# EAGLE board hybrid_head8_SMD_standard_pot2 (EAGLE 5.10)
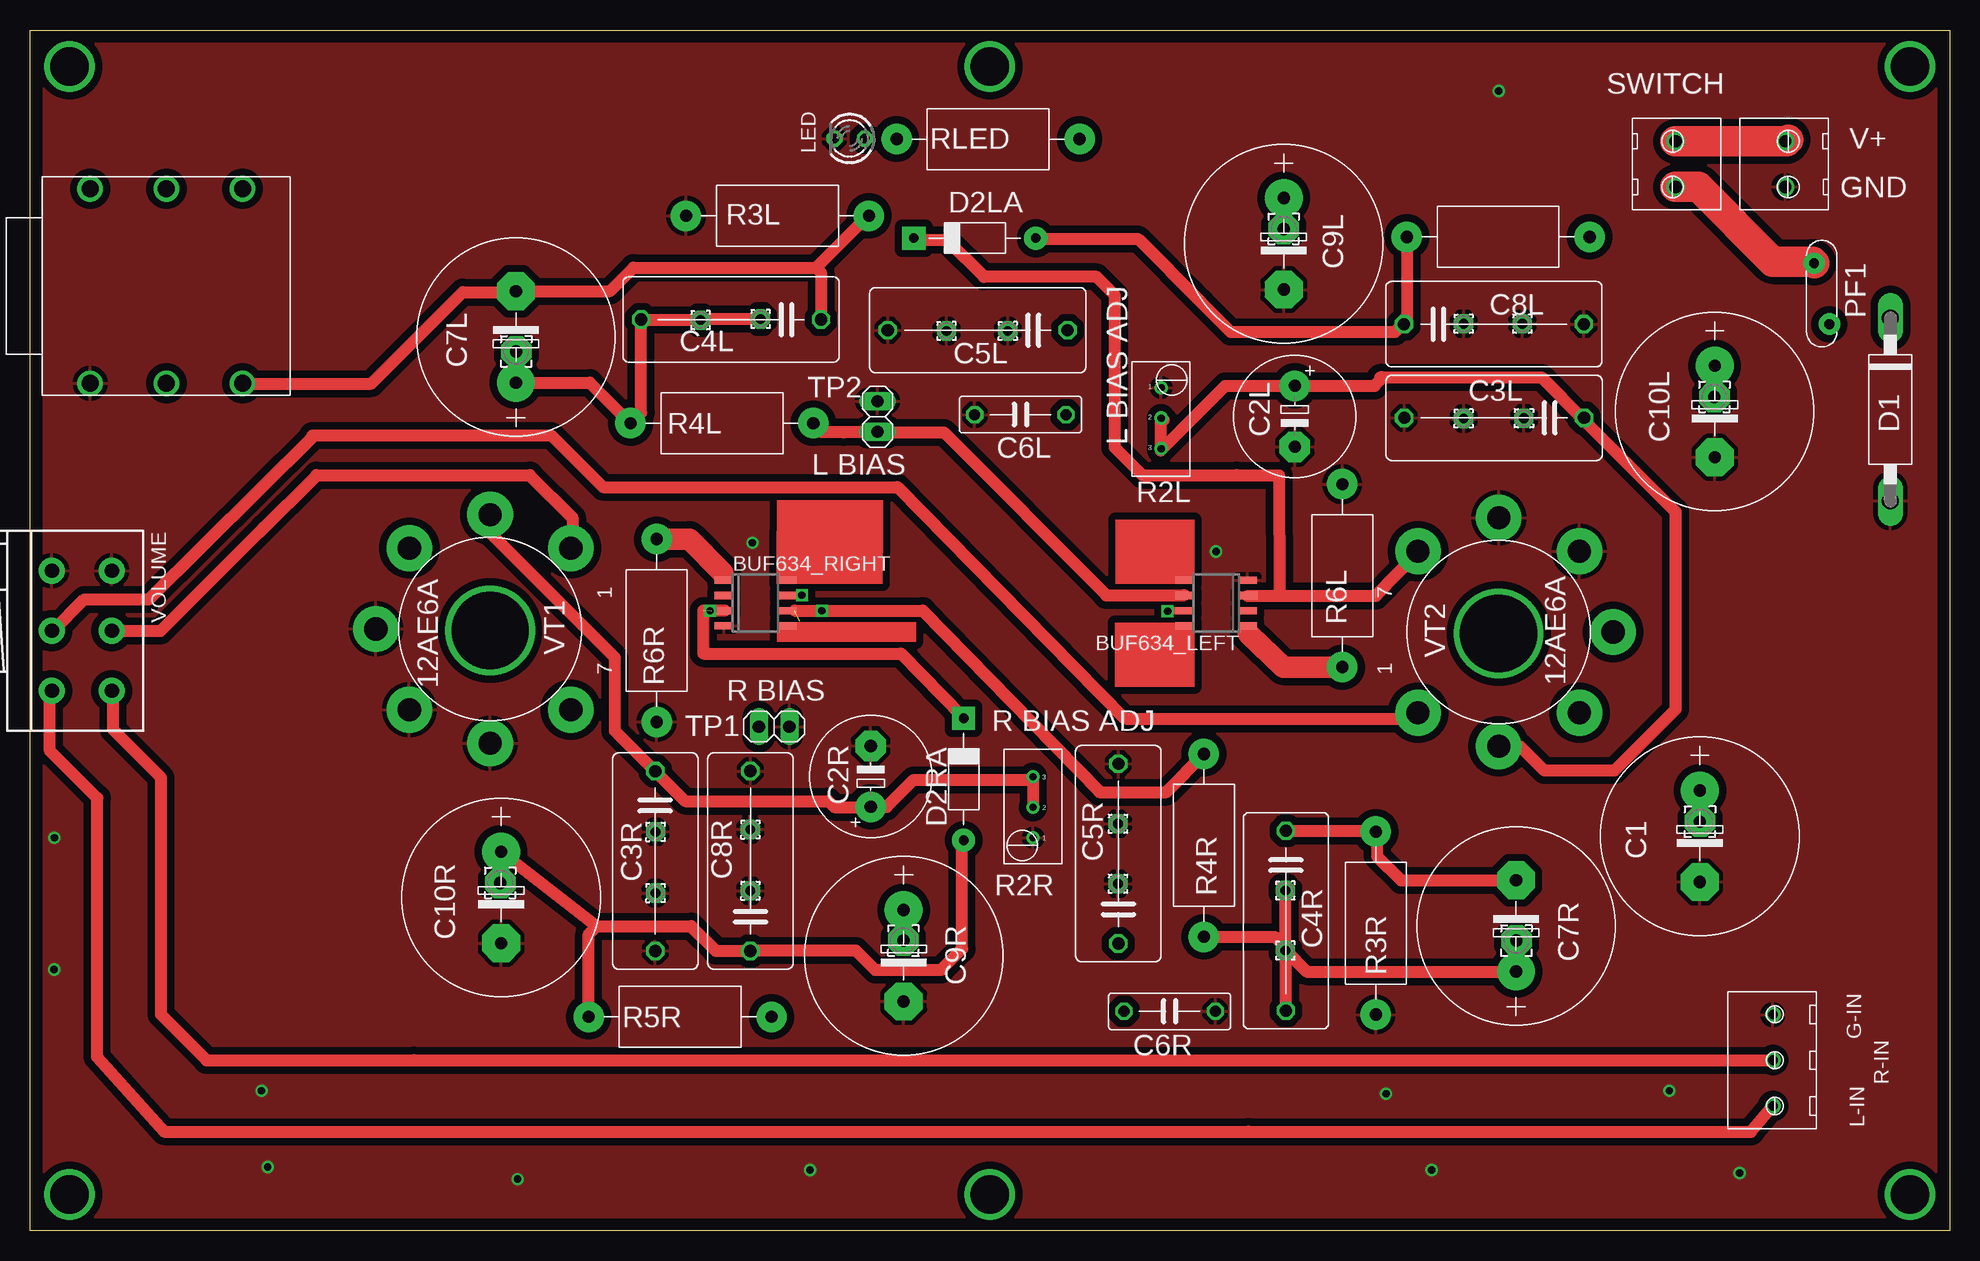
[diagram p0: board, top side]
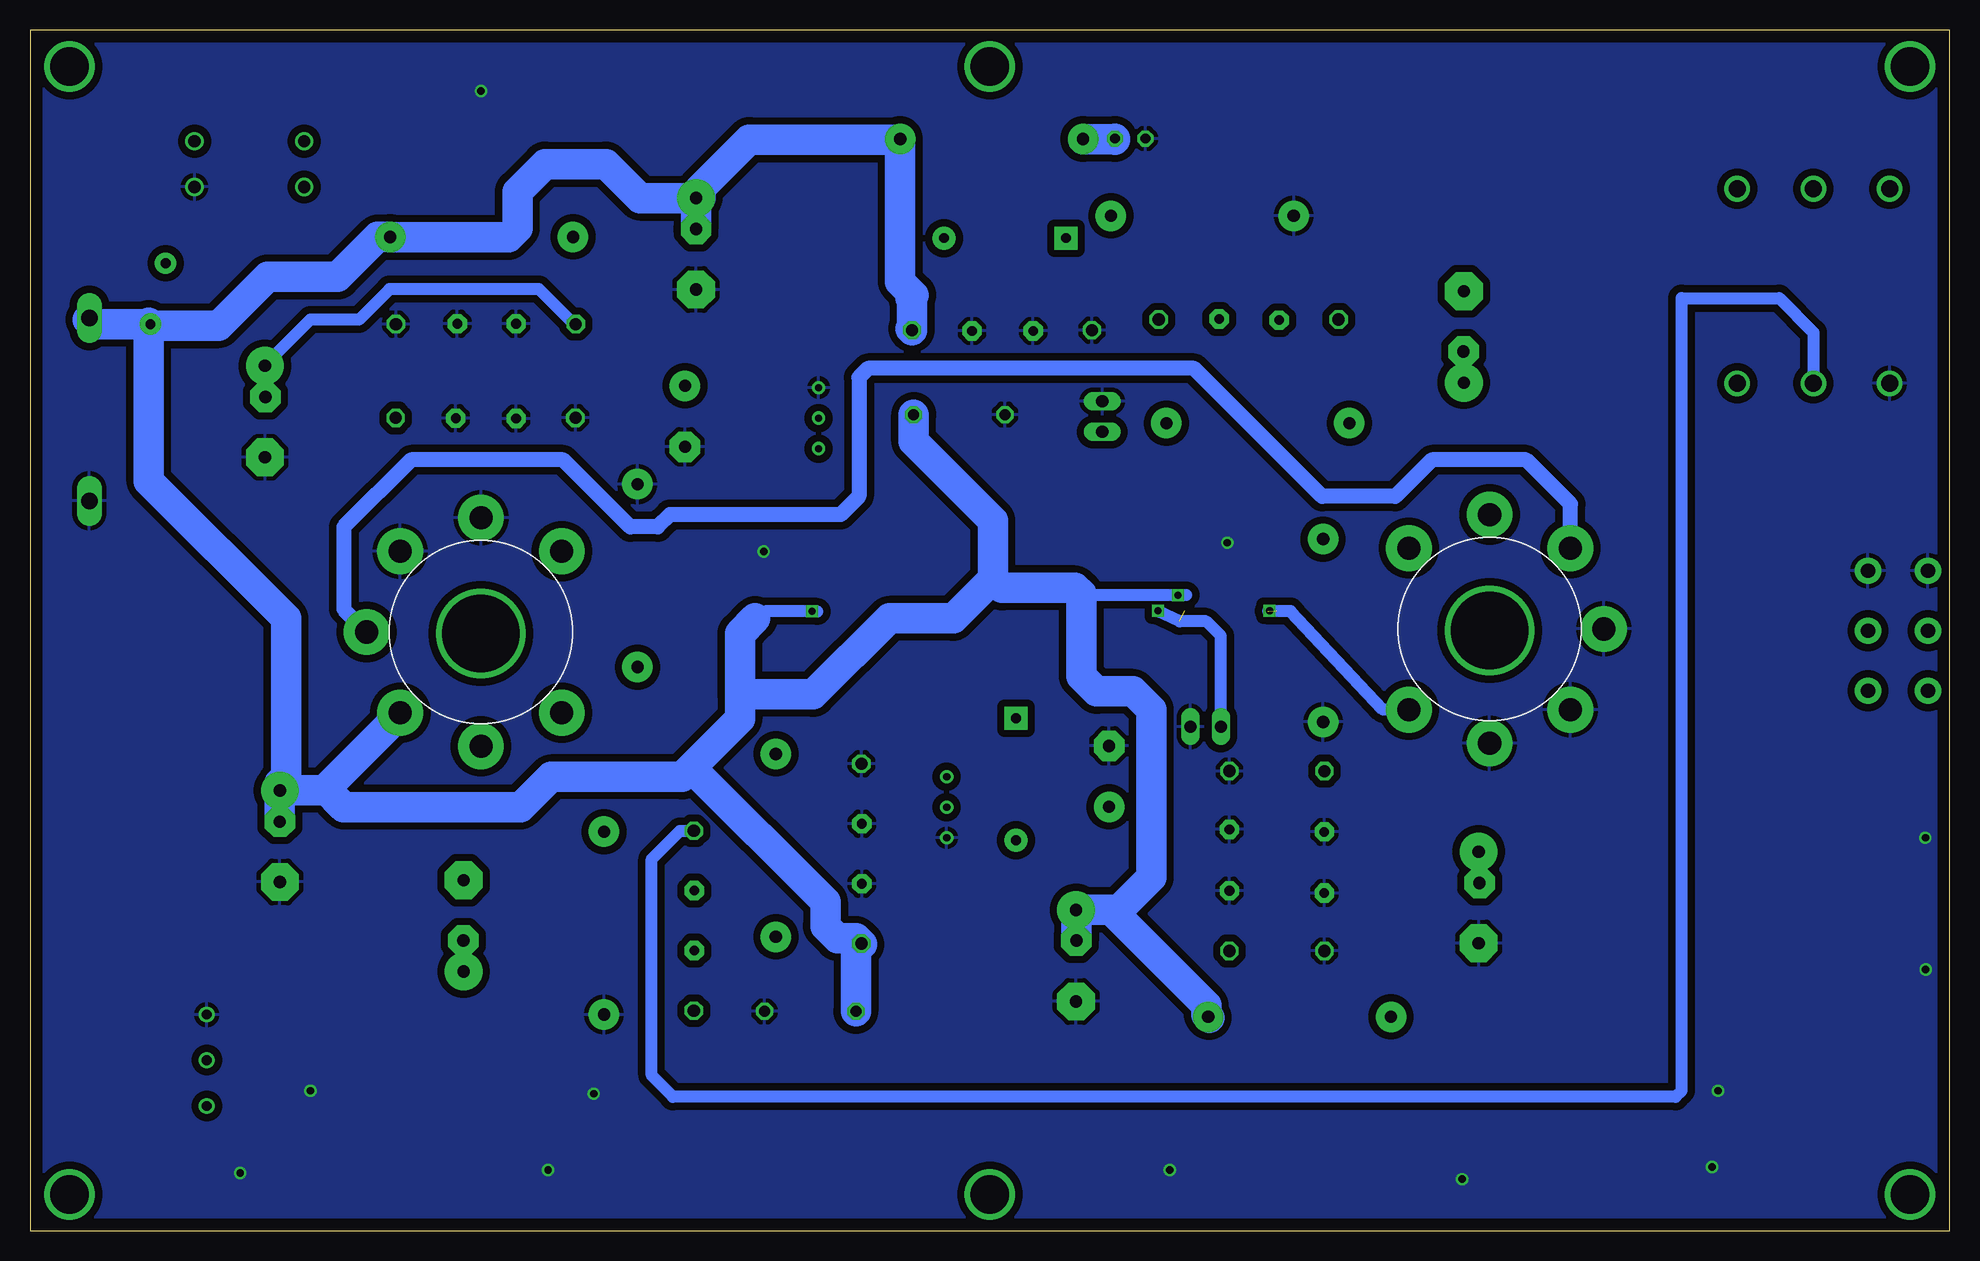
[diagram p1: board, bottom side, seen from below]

Size 160.02 x 100.08 mm. Coordinates in mm from the lower left corner, seen from the top.
Outline: 0,100.08 160.02,100.08 160.02,0 0,0 0,100.08
Copper layers (1*16): Top 0.035mm / dielectric 1.5mm / Bottom 0.035mm
Design rules "default": minimum track width 10mil, minimum drill 24mil, track to track 20mil, track to pad 20mil, pad to pad 20mil, via to via 20mil, smd to smd 8mil, copper to edge 40mil, drill to drill 8mil, minimum pad ring 10mil, minimum via ring 8mil, stop-mask expansion 0mil, vias tented up to drill 0mil, thermal gap 15mil

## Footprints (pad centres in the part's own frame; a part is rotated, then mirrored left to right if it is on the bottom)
SO8 = smd 0.6 x 1.6: 1 -1.905,-2.6; 2 -0.635,-2.6; 3 0.635,-2.6; 4 1.905,-2.6; 5 1.905,2.6; 6 0.635,2.6; 7 -0.635,2.6; 8 -1.905,2.6
E7,5-16 = drill 1.016 pad 3.15 round: + -3.81,0 | drill 1.016 pad 3.15 octagon: - 3.81,0
E5-10,5 = drill 1.016 pad 2.54 round: + -2.54,0 | drill 1.016 pad 2.54 octagon: - 2.54,0
C150-072X183 = drill 1.016 octagon: 1 -7.493,0; 2 7.493,0
C075-032X103 = drill 0.914 octagon: 1 -3.81,0; 2 3.81,0
CB417-15 = drill 1.397 long: A 7.62,0; K -7.62,0
DO35 = drill 0.813 pad 1.93 square: 1 -5.08,0 | drill 0.813 pad 1.93 round: 2 5.08,0
2,54/1,0 = drill 1.016 pad 2.54 octagon: 1 0,0
1,6/0,8 = drill 0.813 pad 1.6 octagon: 1 0,0
158-PO2EK381V2 = drill 1.016 round: P$1 1.905,0; P$2 -1.905,0
158-P02EK381V3 = drill 0.813 round: P$1 0,0; P$2 -3.81,0; P$3 3.81,0
NMJ6HCD2 = drill 1.422 round: P$1 -8.11,4; P$2 8.11,4; P$3 8.11,10.35; P$4 -8.11,10.35; P$5 -8.11,16.7; P$6 8.11,16.7
LED3MM = drill 0.813 octagon: A -1.27,0; K 1.27,0
RXE050 = drill 0.813 pad 1.778 round: P$1 -0.635,2.54; P$2 0.635,-2.54
3296W = drill 0.6 round: P$1 2.413,7.239; P$2 2.413,4.699; P$3 2.413,2.159
R1/2W = drill 1.016 pad 2.54 round: P$1 0,0; P$2 15.24,0
1X02 = drill 1.016 long: 1 -1.27,0; 2 1.27,0
3RP/1610G = drill 1.2 pad 2.184 round: 1-1 -5,0; 1-2 0,0; 1-3 5,0; 2-1 -5,5; 2-2 0,5; 2-3 5,5
MINI7_PCB = drill 1.93 pad 3.81 round: 1 6.731,-6.731; 2 9.525,0; 3 6.731,6.731; 4 0,9.525; 5 -6.731,6.731; 6 -9.525,0; 7 -6.731,-6.731

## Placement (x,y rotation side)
BUF634_LEFT  [SO8]  98.87,52.32 90 top
BUF634_RIGHT  [SO8]  60.45,52.32 270 top
C1  100UF_100V  [E7,5-16]  139.19,32.89 270 top
C2L  220UF_16V  [E5-10,5]  105.43,67.89 270 top
C2R  220UF_16V  [E5-10,5]  70.08,37.87 90 top
C3L  0.22UF_50V  [C150-072X183]  122.04,67.75 180 top
C3R  0.22UF_50V  [C150-072X183]  52.12,30.82 270 top
C4L  0.22UF_50V  [C150-072X183]  58.44,75.95 180 top
C4R  0.22UF_50V  [C150-072X183]  104.69,25.85 270 top
C5L  0.22UF_50V  [C150-072X183]  79,75.06 180 top
C5R  0.22UF_50V  [C150-072X183]  90.72,31.44 90 top
C6L  .01UF_50V  [C075-032X103]  82.56,68.03 0 top
C6R  .01UF_50V  [C075-032X103]  94.99,18.3 180 top
C7L  100UF_100V  [E7,5-16]  40.51,74.5 90 top
C7R  100UF_100V  [E7,5-16]  123.87,25.42 90 top
C8L  0.22UF_50V  [C150-072X183]  122.02,75.56 0 top
C8R  0.22UF_50V  [C150-072X183]  60.05,30.83 90 top
C9L  100UF_100V  [E7,5-16]  104.51,82.26 270 top
C9R  100UF_100V  [E7,5-16]  72.82,22.93 270 top
C10L  100UF_100V  [E7,5-16]  140.43,68.28 270 top
C10R  100UF_100V  [E7,5-16]  39.27,27.79 270 top
D1  P6KE30  [CB417-15]  155.07,68.45 270 top
D2LA  1N5291  [DO35]  78.75,82.73 0 top
D2RA  1N5291  [DO35]  77.83,37.64 270 top
E$2  [2,54/1,0]  40.53,73.29 0 top
E$3  [1,6/0,8]  52.14,33.25 90 top
E$4  [1,6/0,8]  52.14,28.15 90 top
E$5  [1,6/0,8]  60.04,33.45 90 top
E$6  [1,6/0,8]  60.04,28.35 90 top
E$7  [1,6/0,8]  90.68,28.93 90 top
E$9  [1,6/0,8]  90.68,33.93 90 top
E$10  [1,6/0,8]  104.65,28.36 270 top
E$11  [1,6/0,8]  104.65,23.36 270 top
E$12  [1,6/0,8]  124.53,67.72 0 top
E$13  [1,6/0,8]  119.5,67.7 0 top
E$14  [1,6/0,8]  119.5,75.6 0 top
E$15  [1,6/0,8]  124.4,75.6 0 top
E$16  [1,6/0,8]  81.5,75 0 top
E$17  [1,6/0,8]  76.4,75 0 top
E$18  [1,6/0,8]  55.9,75.9 0 top
E$19  [1,6/0,8]  60.9,76 0 top
E$20  [2,54/1,0]  104.5,83.5 0 top
E$21  [2,54/1,0]  140.4,69.5 0 top
E$22  [2,54/1,0]  139.2,34.1 0 top
E$23  [2,54/1,0]  123.9,24.2 0 top
E$24  [2,54/1,0]  72.8,24.2 0 top
E$25  [2,54/1,0]  39.2,29 0 top
E$26  [158-PO2EK381V2]  137.16,88.9 270 top
E$29  [158-PO2EK381V2]  146.3,88.9 90 top
E$30  [158-P02EK381V3]  145.29,14.22 90 top
E$31  [NMJ6HCD2]  1.02,78.74 270 top
LED  [LED3MM]  68.32,91.03 180 top
PF1  RXE050  [RXE050]  149.35,78.11 0 top
R2  [3296W]  81.19,30.6 0 top
R3L  1K  [R1/2W]  54.69,84.59 0 top
R3R  1K  [R1/2W]  112.18,18.03 90 top
R4L  22  [R1/2W]  65.29,67.31 180 top
R4R  22  [R1/2W]  97.85,39.75 270 top
R5L  1K  [R1/2W]  114.76,82.83 0 top
R5R  1K  [R1/2W]  46.57,17.83 0 top
R6  [3296W]  96.7,72.43 180 top
R6L  1K  [R1/2W]  109.38,46.98 90 top
R6R  1K  [R1/2W]  52.23,42.41 90 top
RLED  1K  [R1/2W]  87.48,90.99 180 top
TP1  [1X02]  62.02,42.02 0 top
TP2  [1X02]  70.64,67.86 90 top
VOLUME  [3RP/1610G]  1.82,50.01 270 top
VT1  12AE6A  [MINI7_PCB]  38.35,50.16 90 top
VT2  12AE6A  [MINI7_PCB]  122.43,49.91 270 top

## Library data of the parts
BUF634_LEFT BUF634_RIGHT = micro-philips
C1 C7L C7R C9L C9R C10L C10R = polcap
C2L C2R C3L C3R C4L C4R C5L C5R C6L C6R C8L C8R = rcl
D1 = diode
D2LA D2RA PF1 R3L R3R R4L R4R R5L R5R R6L R6R RLED VT1 VT2 = wheat
E$2-E$7 E$9-E$25 = wirepad2
E$26 E$29 E$30 = con-kobiconn2
E$31 = neutrik
LED = led
R2 R6 = bourns
TP1 TP2 = pinhead
VOLUME = pot

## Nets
B+L: C8L.1 C10L.+ E$21.1 R5L.P$1
B+R: C8R.1 C10R.+ D2RA.2 E$25.1 R5R.P$1
BUF_L: R4L.P$1 TP2.1
BUF_R: TP1.1
CAP_L: C4L.2 C7L.+ E$2.1 E$18.1 E$19.1 R4L.P$2
CAP_R: C4R.2 C7R.+ E$10.1 E$11.1 E$23.1 R4R.P$2
DCSW: E$26.P$1 PF1.P$1
GND: BUF634_LEFT.4 BUF634_RIGHT.4 C1.- C2L.- C2R.- C3L.2 C3R.2 C5L.2 C5R.2 C6L.1 C6R.1 C8L.2 C8R.2 C9L.- C9R.- C10L.- C10R.- D1.A E$3.1 E$4.1 E$5.1 E$6.1 E$7.1 E$9.1 E$12.1 E$13.1 E$14.1 E$15.1 E$16.1 E$17.1 E$29.P$2 E$30.P$3 E$31.P$2 LED.K R2.P$3 R3L.P$1 R3R.P$1 R6.P$3 R6L.P$2 R6R.P$1 TP1.2 TP2.2 VOLUME.1-1 VOLUME.2-1 VT1.4 VT1.5 VT1.6 VT2.5 VT2.6
K_L: C2L.+ C3L.1 R6.P$1 R6.P$2 VT2.2
K_R: C2R.+ C3R.1 R2.P$1 R2.P$2 VT1.2
L_IN: E$30.P$2
LED: LED.A RLED.P$2
OUT_L: C4L.1 C7L.- E$31.P$6 R3L.P$2
OUT_R: C4R.1 C7R.- E$31.P$3 R3R.P$2
P_L: D2LA.1
P_R: VT1.7
R_IN: E$30.P$1
RIGHT_SIGNAL: VT1.1
S$1: VT1.3 VT2.4
S$17: VT2.7
S$22: D2RA.1
S$23: R4R.P$1
S$25: VT2.1
S$28: R6L.P$1
V+: C1.+ C5L.1 C5R.1 C6L.2 C6R.2 C9L.+ C9R.+ D1.K E$20.1 E$22.1 E$24.1 PF1.P$2 R5L.P$2 R5R.P$2 RLED.P$1 VT2.3
V_IN: E$26.P$2 E$29.P$1

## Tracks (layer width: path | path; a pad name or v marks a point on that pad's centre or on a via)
B+L
  Top 1.016: E$21.1 140.43,69.53 | C10L.+ 140.51,72.08 | R5L.P$1 114.78,82.8 114.81,82.8 114.81,75.95 114.53,75.67 | 114.53,75.42 C8L.1 114.53,75.67 | 114.53,75.67 113.79,74.93 100.08,74.93 96.77,78.23
  Bottom 1.016: E$21.1 140.4,69.53 140.46,69.6 140.43,69.63 C10L.+ 140.43,72.1 140.46,72.14 136.65,75.95 132.59,75.95 130.05,78.49 117.6,78.49 114.55,75.44 114.53,75.46 C8L.1
B+R
  Top 1.016: 47.24,25.4 55.12,25.4 57.19,23.33 C8R.1 59.98,23.33 59.94,23.37 68.83,23.37 70.45,21.75 75.95,21.75 77.7,23.5 77.7,32.49 77.78,32.56 D2RA.2 | 47.24,25.4 39.37,31.5 39.22,31.6 C10R.+ 39.2,31.6 E$25.1 | 47.24,25.4 46.57,24.73 R5R.P$1
BUF_L
  Top 1.016: 70.61,66.55 TP2.1 67.82,66.59 | 67.82,66.59 67.82,66.55 | 67.82,66.59 66,66.59 65.28,67.31 R4L.P$1
BUF_R  (1 unrouted)
  Top 1.016: 89.13,36.58 74.4,51.7 63.73,51.7
  Bottom 1.016: 65.98,51.63 64.19,50.8 61.98,50.8 60.75,49.58 TP1.1
CAP_L
  Top 1.016: 50.04,67.31 46.66,70.69 C7L.+ 40.5,73.29 E$2.1 | E$19.1 55.93,76 55.88,75.95 | 55.88,75.95 55.9,75.93 E$18.1 | 55.88,75.95 C4L.2 50.95,68.22 50.04,67.31 | 50.04,67.31 R4L.P$2
  Bottom 1.016: R4L.P$2 50.04,67.31
CAP_R
  Top 1.016: E$11.1 104.9,23.36 104.9,23.37 103.76,24.51 R4R.P$2 | C4R.2 104.69,18.33 104.65,18.29 E$11.1 | 104.65,28.45 E$10.1 | E$11.1 104.65,28.45 | 104.65,28.45 104.39,28.7 | E$11.1 | E$11.1 106.4,21.61 C7R.+ 123.87,24.17 E$23.1
DCSW
  Top 2.54: E$26.P$1 139.06,87 145.29,80.77 148.59,80.77 PF1.P$1
GND  (via drill 0.61)
  other vias: 2.01,21.78 116.84,5.08 136.65,11.68 122.43,95 2.03,32.77 142.49,4.83 19.81,5.33 40.64,4.32 19.3,11.68 65.02,5.08 113.03,11.43 98.87,56.61 60.22,57.35
  pour Top (isolate 0.61): 0,0 160.02,0 160.02,100.08 0,100.08
  pour Bottom (isolate 0.61): 0,0 160.02,0 160.02,100.08 0,100.08
K_L
  Top 1.016: 105.32,70.44 105.41,70.36 105.43,70.37 C2L.+ | C2L.+ 112.08,70.43 112.78,71.12 | 112.78,71.12 125.73,71.12 | 112.78,71.12 112.52,71.12 | 112.78,71.12 125.98,71.12 129.54,67.57 | 129.54,67.57 129.54,67.56 | 129.54,67.57 C3L.1 | 129.54,67.57 137.16,59.94 137.16,43.43 132.08,38.35 126.24,38.35 124.21,40.39 VT2.2 | 94.49,67.56 94.32,67.73 R6.P$2 94.28,65.33 94.23,65.28 94.28,65.23 R6.P$1 94.28,65.08 | 94.28,65.08 94.23,65.02 | C2L.+ 99.64,70.43 94.28,65.08
K_R
  Top 1.016: C2R.+ | R2.P$2 83.57,35.3 83.57,35.31 83.61,35.35 R2.P$1 83.57,37.84 83.57,37.85 83.31,37.59 73.66,37.59 71.4,35.33 C2R.+ | VT1.2 38.35,58.17 48.77,47.75 48.77,41.66 C3R.1 54.62,35.81 66.55,35.81 67.06,35.31 70.1,35.31 C2R.+
L_IN
  Top 1.016: E$30.P$2 143.45,8.26 101.6,8.27 11.18,8.27 5.59,14.48 5.61,14.5 5.61,36.09
LED
  Bottom 2.54: LED.A 69.59,90.94 69.6,90.93 69.66,90.99 RLED.P$2
LEFT_SIGNAL
  Top 1.016: 91.24,42.69 72.31,61.98 47.75,61.98 43.43,66.29 23.56,66.29
OUT_L
  Top 1.016: R3L.P$2 69.86,84.59 65.53,80.26 | C4L.1 65.93,79.86 65.53,80.26 | 65.53,80.26 50.29,80.26 48.34,78.31 C7L.- 40.56,78.31 40.64,78.23 36.07,78.23 28.45,70.61 17.78,70.61 17.76,70.63 E$31.P$6
OUT_R
  Top 1.016: 123.95,29.21 124.21,29.21 124.18,29.23 C7R.- 123.93,29.23 123.95,29.21 | 123.95,29.21 114.3,29.21 112.27,31.24 112.27,33.27 R3R.P$2 112.18,33.37 112.01,33.53 111.83,33.34 C4R.1
  Bottom 1.016: E$31.P$3 11.37,70.68 11.18,70.87 11.37,71.06 11.37,74.87 14.22,77.72 22.35,77.72 | C4R.1 105.85,33.34 108.2,30.99 108.2,12.95 106.43,11.18 22.86,11.18 22.35,11.68 22.35,77.72 | 22.35,77.72 22.35,77.74
P_L
  Top 1.016: D2LA.1 73.67,82.56 73.66,82.55 76.45,82.55 79.5,79.5 88.9,79.5 90.42,77.98 90.42,65.28 92.71,62.99 100.58,62.99 104.11,62.97 104.14,52.99
P_R  (1 unrouted)
  Top 1.016: 77.75,42.84 72.58,48.1 56.14,48.1 56.14,51.66
  Bottom 1.016: 56.82,51.65 54.94,51.65 47.24,43.43 VT1.7
R_IN
  Top 1.016: 145.35,14.23 145.3,14.23 E$30.P$1 32,14.22 27.72,14.21 14.69,14.24
RIGHT_SIGNAL
  Top 1.016: VT1.1 45.21,56.9 45.21,59.44 41.66,62.99 23.88,62.99 19.05,58.17
S$1
  Bottom 1.27: VT2.4 133.86,51.82 133.86,58.67 128.27,64.26 115.57,64.26 109.98,58.67 107.7,58.67 106.68,59.69 92.46,59.69 90.93,61.21 90.93,71.12 90.17,71.88 62.99,71.88 52.32,61.21 46.23,61.21 43.18,64.26 35.31,64.26 31.62,60.58 VT1.3
S$2  (via drill 0.6)
  other vias: 56.69,51.68
S$3
  Bottom 1.016: 63.63,52.97 71.78,52.98
S$4  (via drill 3.2 pad 3.81)
  other vias: 156.72,3.05
S$5  (via drill 3.2 pad 3.81)
  other vias: 156.72,97.03
S$6  (via drill 3.2 pad 3.81)
  other vias: 80.01,97.03
S$7  (via drill 3.2 pad 3.81)
  other vias: 80.01,3.05
S$8  (via drill 3.2 pad 3.81)
  other vias: 3.3,97.03
S$9  (via drill 3.2 pad 3.81)
  other vias: 3.3,3.05
S$10  (via drill 0.6)
  other vias: 64.34,52.97
S$12
  Top 1.778: 52.23,57.64 54.97,57.64 57.78,54.83
S$13  (via drill 6.45 pad 6.45)
  other vias: 38.35,50.04
S$14  (via drill 6.45 pad 6.45)
  other vias: 122.43,49.78
S$15  (via drill 0.6)
  other vias: 66.01,51.69
S$16
  Bottom 1.016: 94.4,51.62 98.75,51.63
S$17
  Top 1.016: VT2.7 115.82,56.64 112.2,52.92 101.49,52.92
S$18
  Top 1.016: 70.75,66.54 76.17,66.54 89.71,52.96 96.22,52.99
S$19
  Top 0.61: 95.55,51.67 94.76,51.67 94.76,51.64
S$20  (via drill 0.6)
  other vias: 94.83,51.63
S$21
  Top 1.016: 56.14,51.7 57.91,51.7
S$22
  Top 1.016: D2RA.1 77.83,42.83
S$23
  Top 1.016: 97.91,39.75 98.04,39.88 | 97.91,39.75 R4R.P$1 | 97.91,39.75 94.74,36.58 89.15,36.58
S$24
  Top 1.016: 83.93,82.66 92.35,82.66 97.57,77.44
S$25
  Top 1.016: 115.57,42.93 115.82,43.18 VT2.1 | VT2.1 115.57,43.18 115.7,43.05 | 115.7,43.05 VT2.1 | 115.82,42.93 115.82,42.67 | 115.82,42.93 115.7,43.05 | 115.82,42.93 115.57,42.67 91.31,42.7
S$26
  Top 1.016: 1.65,45.03 1.65,40.01 5.58,36.08
S$27
  Top 1.016: 6.94,45.05 6.94,41.74 10.92,37.76 10.92,18.02 14.72,14.22
S$28
  Top 1.016: 109.47,46.99 109.47,46.98 R6L.P$1
S$29
  Top 1.016: 6.85,50.01 10.88,50.01 19.48,58.6
S$30
  Top 1.016: 109.39,46.99 109.47,46.99
S$31
  Top 1.778: 109.38,46.97 104.46,46.97 101.56,49.78
V+
  Bottom 2.54: C5L.1 86.61,75.18 86.49,75.31 86.49,77.72 | 86.49,77.72 86.61,77.72 | 86.49,77.86 86.49,77.72 | 86.49,77.86 86.61,77.98 | 86.49,77.86 86.48,77.86 86.36,77.98 87.48,79.1 RLED.P$1 87.57,90.99 87.63,90.93 100.08,90.93 104.14,86.87 104.14,86.11 104.39,86.36 104.51,86.25 C9L.+ | E$20.1 104.5,86.3 104.51,86.29 C9L.+ | C9L.+ 109.19,86.07 112.01,88.9 117.09,88.9 119.38,86.61 119.38,83.57 120.14,82.8 130.05,82.8 130.02,82.83 R5L.P$2 131.04,82.83 134.37,79.5 140.21,79.5 144.27,75.44 149.86,75.44 PF1.P$2 | D1.K 155.19,75.95 154.81,75.56 PF1.P$2 | PF1.P$2 150.11,75.69 | PF1.P$2 150.11,75.44 150.11,62.48 138.68,51.05 138.68,36.83 138.94,36.58 139.06,36.7 C1.+ | E$22.1 C1.+ | C6R.2 91.18,23.37 90.68,23.88 90.72,23.91 | C1.+ 139.19,37.34 | C1.+ 135.51,36.7 135.38,36.83 | 129.03,43.18 128.78,43.43 | 129.03,43.18 VT2.3 | 90.72,23.91 C5R.1 | 135.38,36.83 129.03,43.18 | 135.38,36.83 133.86,35.31 119.13,35.31 116.59,37.85 105.66,37.85 104.9,38.61 | 90.72,23.91 91.19,24.38 92.71,24.38 93.73,25.4 93.73,27.43 104.9,38.61 | 99.57,51.05 100.84,49.78 100.84,44.7 | 104.9,38.61 100.84,42.67 100.84,44.7 | 100.84,44.7 94.74,44.7 88.39,51.05 83.06,51.05 79.76,54.36 | C6L.2 86.37,65.79 79.76,59.18 79.76,54.36 | 79.76,54.36 78.99,53.59 72.9,53.59 72.39,53.09 72.39,46.23 71.12,44.96 68.07,44.96 66.55,43.43 66.55,29.46 69.27,26.74 C9R.+ | E$24.1 72.8,26.7 72.82,26.72 C9R.+ | C9R.+ 69.92,26.74 61.98,18.8 61.98,18.03 61.78,17.83 | 61.78,17.83 61.72,17.78 | R5R.P$2 61.78,17.83
V_IN
  Top 2.54: 146.43,90.81 E$29.P$1 | E$26.P$2 146.43,90.81 | 146.43,90.81 146.56,90.93
VOLUME
  Top 1.016: 23.63,66.25 9.88,52.62 4.53,52.62 1.88,49.98
(copper drawn outside any net)
  shapes: Top area x9

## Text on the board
tPlace: L BIAS ADJ | L BIAS | 12AE6A | 12AE6A | R BIAS | R BIAS ADJ
tNames: SWITCH | V+ | GND | R2L | R2R | G-IN | R-IN | L-IN
tValues: 5K | 5K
